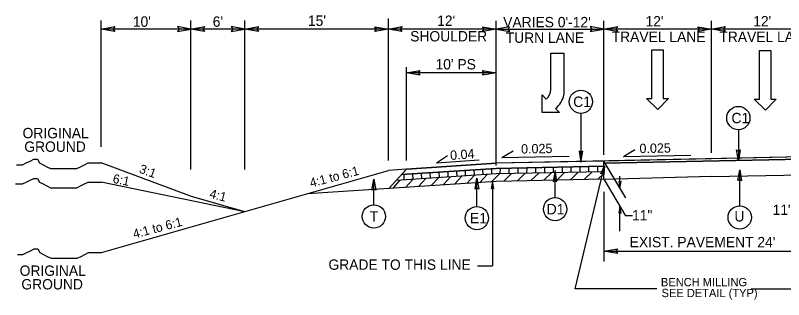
# Model space of a CAD drawing. Extents: x 2176024 to 2177225, y 75947 to 76635.
# Drawn here: x 2176156.3 to 2176241.9, y 76551.8 to 76583.5 of the extents above; entities that cross this region are included whole.
import ezdxf

# ---------------------------------------------------------------- set-up
doc = ezdxf.new("R2010")
doc.units = 0
for name, color, linetype in [('Exist XS Ground Line', 7, 'Continuous'), ('Old_Level_1', 7, 'Continuous'), ('Old_Level_11', 7, 'Continuous'), ('Old_Level_4', 7, 'Continuous'), ('Prop Dimension', 7, 'Continuous'), ('Prop Lane Arrow CELL', 7, 'Continuous'), ('Typical Curb CELL', 7, 'Continuous'), ('Typical Pavement Slope CELL', 7, 'Continuous'), ('Typical Pavement Slope Information CELL', 7, 'Continuous'), ('Typical Shoulder Slope CELL', 7, 'Continuous'), ('Typical Slope Point Local CELL', 7, 'Continuous'), ('Typical Terminator CELL', 7, 'Continuous'), ('Typical Text General CELL', 7, 'Continuous')]:
    doc.layers.add(name, color=color, linetype=linetype)

msp = doc.modelspace()

# ---------------------------------------------------------------- linework, layer by layer
at = {"layer": 'Exist XS Ground Line'}
for q in [(2176221.841, 76565.183), (2176245.841, 76565.736)]:
    msp.add_line((2176233.841, 76565.534), q, dxfattribs=at)
at = {"layer": 'Old_Level_1'}
for p, q in [((2176208.384, 76565.719), (2176208.361, 76566.338)), ((2176209.371, 76565.787), (2176209.349, 76566.403)), ((2176210.306, 76565.826), (2176210.312, 76566.445)), ((2176211.294, 76565.854), (2176211.299, 76566.465)), ((2176212.283, 76565.867), (2176212.288, 76566.486)), ((2176213.28, 76565.891), (2176213.285, 76566.507)), ((2176214.269, 76565.91), (2176214.275, 76566.527)), ((2176215.259, 76565.935), (2176215.264, 76566.548)), ((2176216.24, 76565.955), (2176216.245, 76566.569)), ((2176217.219, 76565.976), (2176217.224, 76566.589)), ((2176218.216, 76565.983), (2176218.221, 76566.61)), ((2176219.205, 76566.012), (2176219.21, 76566.63)), ((2176220.179, 76566.024), (2176220.184, 76566.651)), ((2176221.185, 76566.049), (2176221.191, 76566.672)), ((2176199.602, 76565.141), (2176199.58, 76565.762)), ((2176200.589, 76565.213), (2176200.567, 76565.827)), ((2176201.545, 76565.27), (2176201.522, 76565.889)), ((2176202.532, 76565.338), (2176202.509, 76565.954)), ((2176203.519, 76565.399), (2176203.497, 76566.019)), ((2176203.939, 76564.592), (2176204.767, 76565.482)), ((2176204.504, 76565.472), (2176204.482, 76566.083)), ((2176205.196, 76564.68), (2176206.003, 76565.563)), ((2176205.492, 76565.529), (2176205.469, 76566.148)), ((2176206.442, 76565.59), (2176206.419, 76566.211)), ((2176206.57, 76564.765), (2176207.388, 76565.659)), ((2176207.429, 76565.662), (2176207.406, 76566.275)), ((2176208.014, 76564.863), (2176208.833, 76565.759)), ((2176209.34, 76564.953), (2176210.214, 76565.827)), ((2176210.69, 76565.001), (2176211.556, 76565.853)), ((2176212.188, 76565.017), (2176213.071, 76565.884)), ((2176213.725, 76565.067), (2176214.591, 76565.919)), ((2176215.155, 76565.104), (2176216.012, 76565.947)), ((2176216.613, 76565.131), (2176217.477, 76565.981)), ((2176218.111, 76565.146), (2176218.98, 76566.001)), ((2176219.66, 76565.185), (2176220.526, 76566.037)), ((2176221.17, 76565.222), (2176221.838, 76565.88)), ((2176198.357, 76564.231), (2176199.164, 76565.114)), ((2176199.73, 76564.316), (2176200.548, 76565.21)), ((2176201.175, 76564.414), (2176201.994, 76565.31)), ((2176202.617, 76564.511), (2176203.427, 76565.396))]:
    msp.add_line(p, q, dxfattribs=at)
at = {"layer": 'Old_Level_11'}
for p, q in [((2176219.287, 76572.555), (2176219.287, 76567.14)), ((2176236.832, 76570.741), (2176236.832, 76567.3)), ((2176216.409, 76563.195), (2176216.409, 76566.191)), ((2176236.983, 76562.271), (2176236.983, 76566.271)), ((2176196.216, 76562.383), (2176196.216, 76565.225)), ((2176207.695, 76562.196), (2176207.695, 76565.329))]:
    msp.add_line(p, q, dxfattribs=at)
for points in [[(2176219.08, 76568.34), (2176219.287, 76567.14), (2176219.5, 76568.347), (2176219.287, 76568.194)], [(2176237.039, 76568.5), (2176236.832, 76567.3), (2176236.619, 76568.507), (2176236.832, 76568.353)], [(2176221.52, 76565.825), (2176221.906, 76566.719), (2176221.845, 76565.741), (2176221.708, 76565.9)], [(2176216.616, 76564.991), (2176216.409, 76566.191), (2176216.196, 76564.985), (2176216.409, 76565.138)], [(2176236.776, 76565.071), (2176236.983, 76566.271), (2176237.196, 76565.064), (2176236.983, 76565.217)], [(2176196.01, 76564.025), (2176196.216, 76565.225), (2176196.43, 76564.018), (2176196.216, 76564.172)], [(2176207.488, 76564.129), (2176207.695, 76565.329), (2176207.908, 76564.122), (2176207.695, 76564.275)]]:
    msp.add_lwpolyline(points, close=True, dxfattribs=at)
for centre in [(2176219.287, 76573.851), (2176236.832, 76572.037), (2176216.409, 76561.899), (2176196.216, 76561.087), (2176207.695, 76560.9), (2176236.983, 76560.975)]:
    msp.add_circle(centre, 1.296, dxfattribs=at)
at = {"layer": 'Old_Level_4'}
for p, q in [((2176227.181, 76574.199), (2176227.181, 76579.631)), ((2176227.181, 76579.631), (2176228.462, 76579.631)), ((2176228.462, 76579.631), (2176228.462, 76574.199)), ((2176239.181, 76574.125), (2176239.181, 76579.557)), ((2176239.181, 76579.557), (2176240.462, 76579.557)), ((2176240.462, 76579.557), (2176240.462, 76574.125)), ((2176227.841, 76572.977), (2176226.599, 76574.199)), ((2176226.599, 76574.199), (2176227.181, 76574.199)), ((2176229.044, 76574.199), (2176227.841, 76572.977)), ((2176228.462, 76574.199), (2176229.044, 76574.199)), ((2176239.841, 76572.902), (2176238.599, 76574.125)), ((2176238.599, 76574.125), (2176239.181, 76574.125)), ((2176241.044, 76574.125), (2176239.841, 76572.902)), ((2176240.462, 76574.125), (2176241.044, 76574.125))]:
    msp.add_line(p, q, dxfattribs=at)
at = {"layer": 'Prop Dimension'}
for p, q in [((2176165.841, 76568.827), (2176165.841, 76582.899)), ((2176175.841, 76566.322), (2176175.841, 76582.899)), ((2176181.841, 76566.322), (2176181.841, 76582.899)), ((2176197.841, 76567.311), (2176197.841, 76583.109)), ((2176209.841, 76566.75), (2176209.841, 76582.873)), ((2176221.841, 76567.948), (2176221.841, 76582.873)), ((2176233.841, 76568.149), (2176233.841, 76582.873)), ((2176175.841, 76581.946), (2176165.841, 76581.946)), ((2176181.841, 76581.946), (2176175.841, 76581.946)), ((2176197.841, 76581.946), (2176181.841, 76581.946)), ((2176209.841, 76581.946), (2176197.841, 76581.946)), ((2176209.841, 76581.946), (2176221.841, 76581.946)), ((2176233.841, 76581.946), (2176221.947, 76581.946)), ((2176245.841, 76581.946), (2176233.947, 76581.946)), ((2176199.841, 76567.311), (2176199.841, 76577.691)), ((2176209.841, 76577.073), (2176199.841, 76577.073)), ((2176221.796, 76567.237), (2176224.266, 76563.155)), ((2176218.631, 76553.036), (2176221.906, 76566.719)), ((2176223.629, 76564.23), (2176223.629, 76565.558)), ((2176209.441, 76564.959), (2176209.441, 76555.604)), ((2176221.841, 76565.236), (2176224.266, 76561.141)), ((2176221.841, 76563.819), (2176221.841, 76556.067)), ((2176223.629, 76559.44), (2176223.629, 76562.216)), ((2176225.046, 76561.141), (2176224.266, 76561.141)), ((2176221.841, 76557.222), (2176245.841, 76557.222)), ((2176207.768, 76555.604), (2176209.441, 76555.604)), ((2176227.742, 76553.036), (2176218.631, 76553.036)), ((2176238.271, 76553.036), (2176246.864, 76553.036))]:
    msp.add_line(p, q, dxfattribs=at)
at = {"layer": 'Prop Lane Arrow CELL'}
for p, q in [((2176215.926, 76575.246), (2176215.934, 76579.261)), ((2176215.934, 76579.261), (2176217.382, 76579.259)), ((2176217.382, 76579.259), (2176217.373, 76574.629)), ((2176214.978, 76572.637), (2176214.96, 76574.612)), ((2176214.96, 76574.612), (2176215.42, 76574.15)), ((2176216.909, 76572.656), (2176214.978, 76572.637)), ((2176216.449, 76573.117), (2176216.909, 76572.656))]:
    msp.add_line(p, q, dxfattribs=at)
for centre, radius, start, end in [((2176214.497, 76575.244), 1.437, 310.23549, 359.89367), ((2176215.103, 76574.981), 2.305, 305.9059, 351.2176)]:
    msp.add_arc(centre, radius, start, end, dxfattribs=at)
at = {"layer": 'Typical Curb CELL'}
msp.add_line((2176221.841, 76565.236), (2176221.841, 76567.25), dxfattribs=at)
at = {"layer": 'Typical Pavement Slope CELL'}
for p, q in [((2176245.841, 76567.75), (2176209.841, 76567)), ((2176245.17, 76567.486), (2176221.841, 76567)), ((2176199.86, 76566.345), (2176197.889, 76564.201)), ((2176209.841, 76566.435), (2176199.307, 76565.744)), ((2176199.86, 76566.345), (2176209.841, 76567)), ((2176221.841, 76566.685), (2176209.841, 76566.435)), ((2176209.841, 76565.818), (2176198.703, 76565.087)), ((2176221.841, 76566.068), (2176209.841, 76565.818)), ((2176181.841, 76561.611), (2176165.841, 76564.906)), ((2176209.841, 76564.986), (2176188.831, 76563.607))]:
    msp.add_line(p, q, dxfattribs=at)
at = {"layer": 'Typical Pavement Slope Information CELL'}
for p, q in [((2176210.482, 76567.632), (2176211.743, 76568.394)), ((2176224.027, 76567.77), (2176225.288, 76568.532)), ((2176203.213, 76567.06), (2176204.436, 76567.882)), ((2176203.213, 76567.06), (2176207.959, 76567.386)), ((2176210.482, 76567.632), (2176217.987, 76567.782)), ((2176224.027, 76567.77), (2176231.533, 76567.92))]:
    msp.add_line(p, q, dxfattribs=at)
at = {"layer": 'Typical Shoulder Slope CELL'}
for p, q in [((2176175.894, 76563.309), (2176165.841, 76567.035)), ((2176199.86, 76566.345), (2176197.86, 76566.185)), ((2176165.887, 76557.055), (2176197.86, 76566.185)), ((2176221.841, 76565.236), (2176209.841, 76564.986)), ((2176181.841, 76561.611), (2176175.894, 76563.309))]:
    msp.add_line(p, q, dxfattribs=at)
at = {"layer": 'Typical Slope Point Local CELL'}
for p, q in [((2176221.841, 76567.25), (2176209.841, 76567)), ((2176233.841, 76567.5), (2176221.841, 76567.25)), ((2176221.841, 76567), (2176245.17, 76567.486)), ((2176221.841, 76566.685), (2176221.841, 76567.25)), ((2176221.841, 76567.25), (2176221.841, 76567)), ((2176245.12, 76567.735), (2176233.841, 76567.5)), ((2176199.307, 76565.744), (2176209.841, 76566.435)), ((2176199.86, 76566.345), (2176199.307, 76565.744)), ((2176209.841, 76567), (2176199.86, 76566.345)), ((2176209.841, 76566.435), (2176221.841, 76566.685))]:
    msp.add_line(p, q, dxfattribs=at)
for points in [[(2176156.406, 76566.827), (2176156.651, 76566.827), (2176157.068, 76566.827), (2176157.486, 76567.035), (2176157.904, 76567.244), (2176158.321, 76567.454), (2176158.739, 76567.454), (2176158.949, 76567.035), (2176159.366, 76566.827), (2176159.784, 76566.617), (2176160.202, 76566.409), (2176160.619, 76566.409), (2176161.037, 76566.409), (2176161.455, 76566.409), (2176161.872, 76566.409), (2176162.29, 76566.409), (2176162.708, 76566.409), (2176163.125, 76566.409), (2176163.543, 76566.617), (2176163.96, 76566.827), (2176164.378, 76567.035), (2176165.005, 76567.035), (2176165.423, 76567.035), (2176165.841, 76567.035)], [(2176156.273, 76564.698), (2176156.651, 76564.698), (2176157.068, 76564.698), (2176157.486, 76564.906), (2176157.904, 76565.115), (2176158.321, 76565.325), (2176158.739, 76565.325), (2176158.949, 76564.906), (2176159.366, 76564.698), (2176159.784, 76564.488), (2176160.202, 76564.28), (2176160.619, 76564.28), (2176161.037, 76564.28), (2176161.455, 76564.28), (2176161.872, 76564.28), (2176162.29, 76564.28), (2176162.708, 76564.28), (2176163.125, 76564.28), (2176163.543, 76564.488), (2176163.96, 76564.698), (2176164.378, 76564.906), (2176165.005, 76564.906), (2176165.423, 76564.906), (2176165.841, 76564.906)], [(2176156.497, 76556.847), (2176156.697, 76556.847), (2176157.115, 76556.847), (2176157.533, 76557.055), (2176157.95, 76557.265), (2176158.368, 76557.475), (2176158.786, 76557.475), (2176158.995, 76557.055), (2176159.413, 76556.847), (2176159.831, 76556.638), (2176160.248, 76556.43), (2176160.666, 76556.43), (2176161.084, 76556.43), (2176161.501, 76556.43), (2176161.919, 76556.43), (2176162.337, 76556.43), (2176162.754, 76556.43), (2176163.172, 76556.43), (2176163.589, 76556.638), (2176164.007, 76556.847), (2176164.425, 76557.055), (2176165.052, 76557.055), (2176165.47, 76557.055), (2176165.887, 76557.055)]]:
    msp.add_lwpolyline(points, dxfattribs=at)
at = {"layer": 'Typical Terminator CELL'}
for points in [[(2176167.35, 76581.686), (2176165.841, 76581.946), (2176167.359, 76582.214), (2176167.166, 76581.946)], [(2176174.331, 76581.686), (2176175.841, 76581.946), (2176174.323, 76582.214), (2176174.516, 76581.946)], [(2176177.35, 76581.686), (2176175.841, 76581.946), (2176177.359, 76582.214), (2176177.166, 76581.946)], [(2176180.331, 76581.686), (2176181.841, 76581.946), (2176180.323, 76582.214), (2176180.516, 76581.946)], [(2176183.35, 76581.686), (2176181.841, 76581.946), (2176183.359, 76582.214), (2176183.166, 76581.946)], [(2176196.331, 76582.206), (2176197.841, 76581.946), (2176196.323, 76581.677), (2176196.516, 76581.946)], [(2176199.35, 76581.686), (2176197.841, 76581.946), (2176199.359, 76582.214), (2176199.166, 76581.946)], [(2176208.331, 76582.206), (2176209.841, 76581.946), (2176208.323, 76581.677), (2176208.516, 76581.946)], [(2176211.35, 76582.206), (2176209.841, 76581.946), (2176211.359, 76581.677), (2176211.166, 76581.946)], [(2176220.331, 76581.686), (2176221.841, 76581.946), (2176220.323, 76582.214), (2176220.516, 76581.946)], [(2176223.35, 76581.686), (2176221.841, 76581.946), (2176223.359, 76582.214), (2176223.166, 76581.946)], [(2176223.35, 76581.686), (2176221.841, 76581.946), (2176223.359, 76582.214), (2176223.166, 76581.946)], [(2176232.331, 76582.206), (2176233.841, 76581.946), (2176232.323, 76581.677), (2176232.516, 76581.946)], [(2176235.35, 76581.686), (2176233.841, 76581.946), (2176235.359, 76582.214), (2176235.166, 76581.946)], [(2176201.35, 76576.814), (2176199.841, 76577.073), (2176201.359, 76577.342), (2176201.166, 76577.073)], [(2176208.331, 76577.333), (2176209.841, 76577.073), (2176208.323, 76576.805), (2176208.516, 76577.073)], [(2176209.571, 76564.205), (2176209.441, 76564.959), (2176209.307, 76564.2), (2176209.441, 76564.297)], [(2176223.497, 76564.984), (2176223.629, 76564.23), (2176223.761, 76564.989), (2176223.627, 76564.892)], [(2176223.761, 76561.462), (2176223.629, 76562.216), (2176223.497, 76561.457), (2176223.631, 76561.554)], [(2176223.35, 76556.962), (2176221.841, 76557.222), (2176223.359, 76557.491), (2176223.166, 76557.222)]]:
    msp.add_lwpolyline(points, close=True, dxfattribs=at)

# ---------------------------------------------------------------- texts
at = {"layer": 'Old_Level_11'}
for s, rotation, p in [('C1', 359.99974, (2176218.431, 76573.271)), ('C1', 0.00026, (2176236.063, 76571.457)), ('D1', 359.99974, (2176215.475, 76561.319)), ('T', 359.99974, (2176195.759, 76560.507)), ('E1', 359.99974, (2176206.931, 76560.32)), ('U', 0.00026, (2176236.397, 76560.521))]:
    msp.add_text(s, height=1.16, rotation=rotation, dxfattribs=at).set_placement(p)
for p in [(2176240.655, 76561.251), (2176224.988, 76560.64)]:
    msp.add_text('11"', height=1.1533, dxfattribs=at).set_placement(p)
at = {"layer": 'Typical Pavement Slope Information CELL'}
for s, rotation, p in [('0.025', 1.14574, (2176212.631, 76568.075)), ('0.025', 1.14574, (2176225.824, 76568.128)), ('0.04', 4.26584, (2176204.754, 76567.362))]:
    msp.add_text(s, height=1.0429, rotation=rotation, dxfattribs=at).set_placement(p)
at = {"layer": 'Typical Slope Point Local CELL'}
for s, rotation, p in [('3:1', 339.63369, (2176169.988, 76565.987)), ('4:1 to 6:1', 14.73365, (2176189.217, 76564.31)), ('6:1', 348.41207, (2176167.062, 76564.841)), ('4:1', 345.26635, (2176177.837, 76563.189)), ('4:1 to 6:1', 14.73365, (2176169.516, 76558.627))]:
    msp.add_text(s, height=1.0064, rotation=rotation, dxfattribs=at).set_placement(p)
at = {"layer": 'Typical Text General CELL'}
for s, height, p in [("15'", 1.1533, (2176188.871, 76582.3)), ("12' ", 1.1533, (2176203.268, 76582.296)), ("10'", 1.1533, (2176169.362, 76582.198)), ("6'", 1.1533, (2176178.265, 76582.198)), ("VARIES 0'-12'", 1.15334, (2176210.628, 76582.138)), ("12' ", 1.1533, (2176226.485, 76582.234)), ("12' ", 1.1533, (2176238.485, 76582.234)), ('SHOULDER', 1.1533, (2176200.267, 76580.566)), (' TURN LANE', 1.1533, (2176210.481, 76580.408)), ('TRAVEL LANE', 1.15334, (2176222.715, 76580.504)), ('TRAVEL LANE', 1.15334, (2176234.715, 76580.504)), ("10' PS", 1.1533, (2176203.09, 76577.45)), ('ORIGINAL', 1.1533, (2176157.075, 76569.787)), ('GROUND', 1.1533, (2176157.269, 76568.275)), ("EXIST. PAVEMENT 24'", 1.15334, (2176224.722, 76557.65)), ('GRADE TO THIS LINE', 1.15334, (2176191.16, 76555.144)), ('ORIGINAL', 1.1533, (2176156.752, 76554.47)), ('GROUND', 1.1533, (2176156.945, 76552.958)), ('BENCH MILLING', 0.92267, (2176228.203, 76553.312)), ('SEE DETAIL (TYP)', 0.92267, (2176228.278, 76552.102))]:
    msp.add_text(s, height=height, dxfattribs=at).set_placement(p)

doc.saveas('drawing.dxf')
